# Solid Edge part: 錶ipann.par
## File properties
Author: Türk
Template: iso part.par
Last saved by: Türk
Revision: 23
Application: Solid Edge
Accuracy: 0,990
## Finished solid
Body 1: sheet body, 2 faces, 82 edges, 82 vertices.
  Faces by surface: plane 2
  Edges by curve: line 52, circle 20, ellipse 10
Body 2: sheet body, 1 face, 38 edges, 38 vertices.
  Faces by surface: plane 1
  Edges by curve: line 24, circle 14
Body 3: solid body, 259 faces, 683 edges, 424 vertices.
  Faces by surface: plane 117, cylinder 72, spline 20, torus 20, blend 18, sphere 8, swept 4
  Edges by curve: line 351, circle 166, curve on surface 86, ellipse 44, intersection 28, spline 8
Body 4: sheet body, 50 faces, 120 edges, 80 vertices.
  Faces by surface: plane 50
  Edges by curve: line 120
Bounding box of the edges (mm; curved faces can reach further): 640.000 x 252.243 x 340.013, from (-320, -27.2432, -166.4847) to (320, 225, 173.5283).
Cylindrical faces by radius (mm): R7 x20, R10 x4, R20 x12, R22 x6, R50 x12, R70 x4, R80 x4, R82.5 x10
Toroidal faces (ring radius, tube radius in mm): R77.5 r5 x20
Spherical faces by radius (mm): R20 x4, R50 x4
Planar faces by outward normal: +x 21, +y 10, +z 3, -x 20, -y 2, -z 3, oblique 58
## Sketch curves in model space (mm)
line (-180.9759, 23.2051, -150) -> (241.1352, 23.2051, -150)
line (179.3393, 23.2051, 153.5359) -> (-259.4991, 23.2051, 153.5359)
ellipse centre (199.3354, 39.4939, -147.3931) radii 20.7224, 20 from (199.4238, 34.1305, -127.3769) through (212.9851, 43.4139, -162.023) to (179.3356, 39.4702, -147.3047)
ellipse centre (-200.6607, 39.02, -145.6247) radii 20.7224, 20 from (-180.6609, 39.0437, -145.7131) through (-215.2787, 42.6804, -159.2855) to (-200.5723, 33.6567, -125.6085)
line (199.5446, 26.7949, -100) -> (199.4238, 33.8748, -126.4225)
line (179.3356, 39.0283, -145.6555) -> (-180.6609, 38.6167, -144.1194)
line (-200.5723, 33.4175, -124.7158) -> (-200.4593, 26.7949, -100)
ellipse centre (-250, -5.359, 20) radii 82.8221, 80 from (-250, -26.7949, 100) through (-287.8303, -24.2468, 90.4902) to (-316.6667, -17.2081, 64.2217)
line (-250, -26.7949, 100) -> (250, -26.7949, 100)
ellipse centre (250, -5.359, 20) radii 82.8221, 80 from (316.6667, -17.2081, 64.2217) through (287.8303, -24.2468, 90.4902) to (250, -26.7949, 100)
ellipse centre (-250, 5.359, -20) radii 82.8221, 80 from (-250, 26.7949, -100) through (-287.8303, 24.2468, -90.4902) to (-316.6667, 17.2081, -64.2217)
line (-250, 26.7949, -100) -> (250, 26.7949, -100)
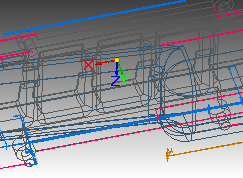
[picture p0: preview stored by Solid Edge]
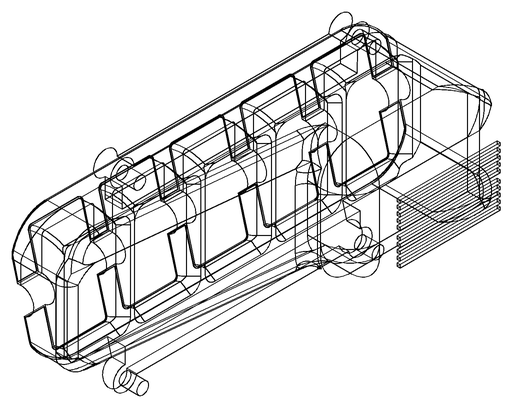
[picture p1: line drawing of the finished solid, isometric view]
